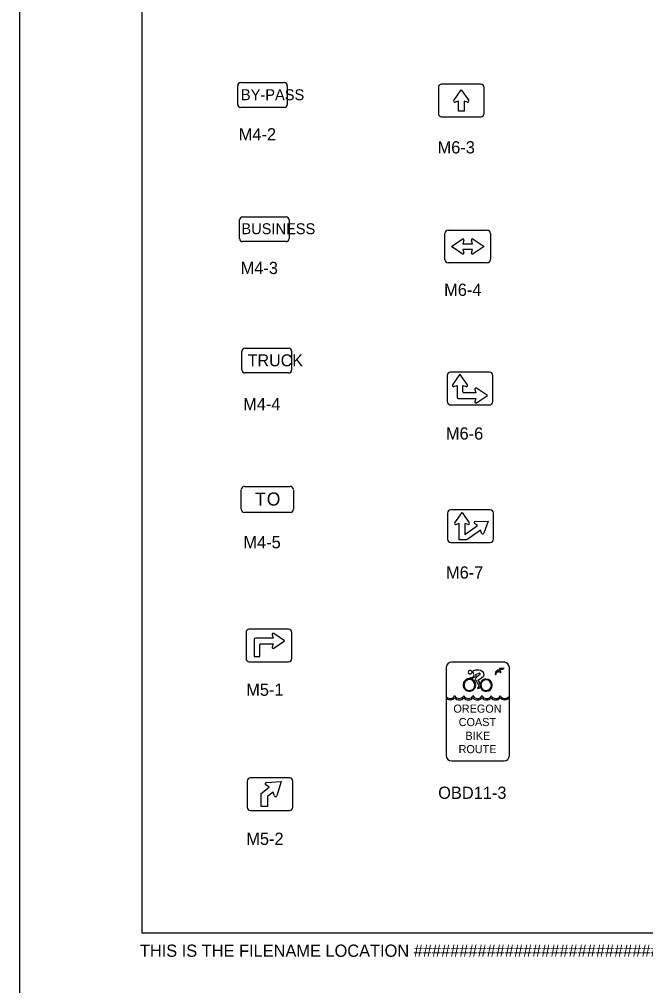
# Model space of a CAD drawing. Extents: x 42133 to 45533, y 41351 to 47951.
# Drawn here: x 42133 to 42517, y 44669 to 45261 of the extents above; entities that cross this region are included whole.
import ezdxf

# ---------------------------------------------------------------- set-up
doc = ezdxf.new("R2010")
doc.units = 0
for name, color, linetype in [('#plot_border', 7, 'Continuous'), ('#plot_shape', 7, 'Continuous'), ('P_ODOT_PLAN_Border', 7, 'Continuous'), ('P_TRAF_SIGN_SignDetails', 7, 'Continuous')]:
    doc.layers.add(name, color=color, linetype=linetype)

msp = doc.modelspace()

# ---------------------------------------------------------------- linework, layer by layer
at = {"layer": '#plot_shape'}
msp.add_lwpolyline([(42133.34, 44651.35), (43833.34, 44651.35), (43833.34, 45751.35), (42133.34, 45751.35)], close=True, dxfattribs=at)
at = {"layer": 'P_ODOT_PLAN_Border'}
msp.add_lwpolyline([(42208.34, 44701.35), (43808.34, 44701.35), (43808.34, 45701.35), (42208.34, 45701.35)], close=True, dxfattribs=at)
at = {"layer": 'P_TRAF_SIGN_SignDetails'}
for p, q in [((42267.07, 45209.07), (42267.07, 45220.48)), ((42268.98, 45222.38), (42295.58, 45222.38)), ((42297.48, 45220.48), (42297.48, 45209.07)), ((42390.03, 45219.48), (42390.03, 45203.48)), ((42416.01, 45221.48), (42392.02, 45221.48)), ((42418.01, 45203.48), (42418.01, 45219.48)), ((42399.47, 45211.36), (42404.01, 45217.99)), ((42404.01, 45217.99), (42408.56, 45211.36)), ((42295.58, 45207.17), (42268.98, 45207.17)), ((42402.27, 45210.97), (42400.21, 45210.35)), ((42402.27, 45204.98), (42402.27, 45210.97)), ((42407.82, 45210.35), (42405.76, 45210.97)), ((42405.76, 45210.97), (42405.76, 45204.98)), ((42392.02, 45201.49), (42416.01, 45201.49)), ((42405.76, 45204.98), (42402.27, 45204.98)), ((42268.18, 45126.87), (42268.18, 45138.27)), ((42270.09, 45140.17), (42296.7, 45140.17)), ((42298.6, 45138.27), (42298.6, 45126.87)), ((42394, 45113.94), (42394, 45129.94)), ((42395.99, 45131.94), (42419.98, 45131.94)), ((42421.98, 45129.94), (42421.98, 45113.94)), ((42296.7, 45124.96), (42270.09, 45124.96)), ((42398, 45121.94), (42404.62, 45126.48)), ((42405.63, 45125.74), (42405.01, 45123.68)), ((42410.97, 45123.68), (42410.35, 45125.74)), ((42411.37, 45126.48), (42417.99, 45121.94)), ((42404.62, 45117.39), (42398, 45121.94)), ((42405.01, 45123.68), (42410.97, 45123.68)), ((42410.97, 45120.19), (42405.01, 45120.19)), ((42405.01, 45120.19), (42405.63, 45118.14)), ((42410.35, 45118.14), (42410.97, 45120.19)), ((42417.99, 45121.94), (42411.37, 45117.39)), ((42419.98, 45111.94), (42395.99, 45111.94)), ((42271.59, 45059.67), (42298.2, 45059.67)), ((42269.69, 45046.37), (42269.69, 45057.77)), ((42300.1, 45057.77), (42300.1, 45046.37)), ((42298.2, 45044.46), (42271.59, 45044.46)), ((42395.36, 45042.85), (42395.36, 45026.86)), ((42421.34, 45044.85), (42397.36, 45044.85)), ((42403.23, 45043.78), (42398.69, 45037.16)), ((42407.78, 45037.16), (42403.23, 45043.78)), ((42423.34, 45026.86), (42423.34, 45042.85)), ((42399.43, 45036.14), (42401.48, 45036.76)), ((42401.48, 45036.76), (42401.48, 45029.59)), ((42404.99, 45032.84), (42404.98, 45036.76)), ((42404.98, 45036.76), (42407.04, 45036.14)), ((42420.05, 45030.59), (42413.44, 45035.14)), ((42413.03, 45032.33), (42405.49, 45032.33)), ((42412.41, 45034.4), (42413.03, 45032.33)), ((42413.44, 45026.04), (42420.05, 45030.59)), ((42397.36, 45024.86), (42421.34, 45024.86)), ((42402.23, 45028.84), (42413.03, 45028.84)), ((42413.03, 45028.84), (42412.41, 45026.78)), ((42413.43, 45026.04), (42413.44, 45026.04)), ((42269.22, 44960.91), (42269.22, 44972.92)), ((42271.22, 44974.92), (42299.23, 44974.92)), ((42301.24, 44972.92), (42301.24, 44960.91)), ((42299.23, 44958.92), (42271.22, 44958.92)), ((42395.69, 44958.55), (42395.69, 44942.56)), ((42421.67, 44960.55), (42397.69, 44960.55)), ((42400.08, 44952.54), (42404.52, 44959.01)), ((42400.08, 44952.54), (42404.52, 44959.01)), ((42400.08, 44952.54), (42404.52, 44959.01)), ((42404.52, 44959.01), (42408.96, 44952.54)), ((42404.52, 44959.01), (42408.96, 44952.54)), ((42404.52, 44959.01), (42408.96, 44952.54)), ((42423.67, 44942.56), (42423.67, 44958.55)), ((42397.69, 44940.56), (42421.67, 44940.56)), ((42298.19, 44887.47), (42274.21, 44887.47)), ((42272.21, 44885.48), (42272.21, 44869.49)), ((42277.19, 44881.23), (42277.19, 44870.6)), ((42288.74, 44881.97), (42277.93, 44881.97)), ((42288.12, 44884.03), (42288.74, 44881.97)), ((42295.75, 44880.23), (42289.14, 44884.77)), ((42300.19, 44869.49), (42300.19, 44885.48)), ((42280.69, 44870.6), (42280.69, 44877.97)), ((42281.2, 44878.48), (42288.74, 44878.48)), ((42288.74, 44878.48), (42288.12, 44876.42)), ((42289.14, 44875.68), (42295.75, 44880.23)), ((42277.19, 44870.6), (42280.69, 44870.6)), ((42274.21, 44867.49), (42298.19, 44867.49)), ((42394.82, 44863.94), (42394.82, 44809.76)), ((42430.64, 44867.15), (42398.03, 44867.15)), ((42433.51, 44809.8), (42433.51, 44864.13)), ((42410.67, 44860.91), (42410.63, 44860.74)), ((42405.2, 44853.73), (42405.73, 44853.63)), ((42405.73, 44853.63), (42405.2, 44853.73)), ((42412.41, 44853.03), (42412.88, 44853)), ((42415.58, 44853.62), (42416.02, 44853)), ((42416.16, 44852.22), (42415.74, 44851.84)), ((42419.26, 44856.32), (42419.26, 44856.83)), ((42419.26, 44856.32), (42419.26, 44856.83)), ((42395.04, 44844.79), (42395.02, 44845.86)), ((42419.38, 44849.39), (42419.37, 44849.86)), ((42433.02, 44845.92), (42433.05, 44844.85)), ((42397.95, 44806.68), (42430.27, 44806.68)), ((42272.91, 44794.24), (42272.91, 44778.25)), ((42298.89, 44796.24), (42274.91, 44796.24)), ((42300.89, 44778.25), (42300.89, 44794.24)), ((42274.91, 44776.25), (42298.89, 44776.25))]:
    msp.add_line(p, q, dxfattribs=at)
for points in [[(42416.51, 44946.22), (42415.86, 44948.2), (42407.41, 44942.14), (42402.83, 44942.14), (42402.83, 44952.15), (42400.84, 44951.52)], [(42416.51, 44946.22), (42415.86, 44948.2), (42407.41, 44942.14), (42402.83, 44942.14), (42402.83, 44952.15), (42400.84, 44951.52)], [(42416.51, 44946.22), (42415.86, 44948.2), (42407.41, 44942.14), (42402.83, 44942.14), (42402.83, 44952.15), (42400.84, 44951.52)], [(42408.19, 44951.52), (42406.21, 44952.15), (42406.21, 44945.43), (42413.89, 44950.94), (42412.22, 44952.19)], [(42408.19, 44951.52), (42406.21, 44952.15), (42406.21, 44945.43), (42413.89, 44950.94), (42412.22, 44952.19)], [(42408.19, 44951.52), (42406.21, 44952.15), (42406.21, 44945.43), (42413.89, 44950.94), (42412.22, 44952.19)], [(42412.61, 44953.41), (42420.45, 44953.57), (42417.79, 44946.2)], [(42412.61, 44953.41), (42420.45, 44953.57), (42417.79, 44946.2)], [(42412.61, 44953.41), (42420.45, 44953.57), (42417.79, 44946.2)], [(42284.66, 44793.46), (42293.79, 44794.1), (42291.09, 44785.35)], [(42284.66, 44793.46), (42293.79, 44794.1), (42291.09, 44785.35)], [(42284.66, 44793.46), (42293.79, 44794.1), (42291.09, 44785.35)], [(42289.61, 44785.31), (42288.74, 44787.58), (42285.36, 44784.9), (42285.36, 44778.82), (42281.42, 44778.82), (42281.42, 44786.8), (42286.3, 44790.66), (42284.28, 44792.03)], [(42289.61, 44785.31), (42288.74, 44787.58), (42285.36, 44784.9), (42285.36, 44778.82), (42281.42, 44778.82), (42281.42, 44786.8), (42286.3, 44790.66), (42284.28, 44792.03)], [(42289.61, 44785.31), (42288.74, 44787.58), (42285.36, 44784.9), (42285.36, 44778.82), (42281.42, 44778.82), (42281.42, 44786.8), (42286.3, 44790.66), (42284.28, 44792.03)]]:
    msp.add_lwpolyline(points, dxfattribs=at)
for centre, radius, start, end in [((42268.97, 45220.48), 1.9, 90, 180), ((42295.58, 45220.48), 1.9, 0, 90), ((42392.02, 45219.48), 2, 90, 180), ((42416.01, 45219.48), 2, 360, 90), ((42268.97, 45209.07), 1.9, 180, 270), ((42295.58, 45209.07), 1.9, 270, 0), ((42400.02, 45210.99), 0.666, 145.51241, 286.7372), ((42408.01, 45210.99), 0.666, 253.2628, 34.48759), ((42392.02, 45203.49), 2, 180, 270), ((42416.01, 45203.49), 2, 270, 0), ((42270.08, 45138.27), 1.9, 90, 180), ((42296.69, 45138.27), 1.9, 0, 90), ((42395.99, 45129.93), 2, 90, 180), ((42419.98, 45129.93), 2, 0, 90), ((42270.08, 45126.87), 1.9, 180, 270), ((42296.69, 45126.87), 1.9, 270, 0), ((42404.99, 45125.94), 0.666, 343.2628, 124.48759), ((42410.99, 45125.94), 0.666, 55.51241, 196.7372), ((42404.99, 45117.94), 0.666, 235.51241, 16.7372), ((42410.99, 45117.94), 0.666, 163.2628, 304.48759), ((42395.99, 45113.94), 2, 180, 270), ((42419.98, 45113.94), 2, 270, 360), ((42271.59, 45057.77), 1.9, 90, 180), ((42298.2, 45057.77), 1.9, 0, 90), ((42271.59, 45046.37), 1.9, 180, 270), ((42298.2, 45046.37), 1.9, 270, 0), ((42397.36, 45042.85), 2, 90, 180), ((42421.34, 45042.85), 2, 360, 90), ((42399.23, 45036.78), 0.666, 145.51241, 286.7372), ((42407.23, 45036.78), 0.666, 253.2628, 34.48759), ((42413.05, 45034.59), 0.666, 55.51241, 196.7372), ((42402.23, 45029.59), 0.746, 180, 270), ((42405.49, 45032.84), 0.506, 180, 270), ((42397.36, 45026.86), 2, 180, 270), ((42413.05, 45026.59), 0.666, 163.2628, 304.48759), ((42421.34, 45026.86), 2, 270, 0), ((42271.22, 44972.93), 2, 90, 180), ((42299.23, 44972.93), 2, 360, 90), ((42271.22, 44960.92), 2, 180, 270), ((42299.23, 44960.92), 2, 270, 360), ((42397.69, 44958.55), 2, 90, 180), ((42421.67, 44958.55), 2, 360, 90), ((42397.69, 44942.56), 2, 180, 270), ((42421.67, 44942.56), 2, 270, 0), ((42274.21, 44885.47), 2, 90, 180), ((42298.2, 44885.47), 2, 360, 90), ((42277.93, 44881.22), 0.746, 90, 180), ((42288.76, 44884.22), 0.666, 55.51241, 196.7372), ((42281.2, 44877.97), 0.506, 90, 180), ((42288.76, 44876.23), 0.666, 163.2628, 304.48759), ((42274.21, 44869.48), 2, 180, 270), ((42298.2, 44869.48), 2, 270, 0), ((42398.1, 44863.87), 3.28, 90, 176.98392), ((42398.1, 44863.87), 3.28, 176.98392, 180), ((42427.72, 44863.11), 0.267, 55.09984, 178.03026), ((42426.99, 44794.51), 68.82, 87.32377, 89.26629), ((42429.61, 44863.7), 0.736, 277.87393, 323.3106), ((42430.23, 44863.87), 3.28, 360, 90), ((42409.67, 44857.15), 0.509, 146.6757, 183.53735), ((42411.09, 44852.31), 5.44, 99.74793, 109.64671), ((42410.03, 44859.52), 1.84, 274.30157, 344.79689), ((42411.76, 44856.61), 1.15, 134.17087, 167.71993), ((42418.69, 44840.45), 18.66, 108.0677, 114.45218), ((42412.29, 44861.2), 1.13, 143.40254, 210.69902), ((42410.03, 44859.36), 1.81, 349.95685, 44.56741), ((42414.17, 44854.23), 8.14, 95.65153, 110.03117), ((42420.13, 44851.62), 9.23, 121.24992, 144.13962), ((42411.14, 44859), 1.94, 336.10404, 22.65986), ((42411.1, 44868.83), 9.26, 281.40372, 292.53029), ((42413.81, 44856.57), 5.77, 47.07871, 94.07318), ((42406.92, 44870.59), 16.14, 296.80103, 310.70014), ((42414.97, 44859.77), 0.623, 24.66568, 120.91866), ((42415.23, 44859.86), 0.368, 288.16063, 27.61072), ((42415.71, 44859.79), 2.26, 320.47777, 26.47607), ((42426.16, 44860.16), 1.32, 161.07967, 208.26866), ((42426.39, 44860.68), 1.47, 144.28592, 183.50768), ((42424.73, 44860.14), 0.657, 294.08836, 340.32682), ((42423.61, 44871.79), 10.37, 278.77404, 284.00291), ((42424.92, 44860.08), 0.458, 338.64936, 38.4327), ((42424.61, 44861.01), 0.94, 316.99959, 356.87468), ((42425.24, 44863.3), 2.36, 277.50421, 305.41891), ((42425.65, 44862.87), 0.77, 289.94858, 318.13199), ((42426.11, 44862.44), 0.349, 235.87836, 288.89222), ((42426.11, 44862.12), 0.395, 271.27035, 332.03771), ((42425.68, 44860.06), 2.36, 63.03764, 76.67919), ((42426.14, 44861.74), 0.374, 30.96984, 75.95273), ((42426.81, 44860.34), 1.05, 43.84297, 101.18103), ((42425.88, 44863.8), 1.87, 298.15666, 316.41489), ((42424.89, 44863.75), 2.64, 331.97589, 346.19902), ((42427.96, 44861.41), 0.512, 220.96473, 283.62721), ((42416.1, 44869.73), 13.99, 325.41501, 331.47073), ((42427.92, 44861.79), 0.3, 179.05314, 213.42455), ((42428, 44861.7), 0.335, 193.69222, 253.0807), ((42427.95, 44860.94), 0.446, 18.31889, 96.99566), ((42428.15, 44861.12), 0.227, 251.60885, 345.61206), ((42429.25, 44869.64), 6.65, 262.65616, 269.96826), ((42429.45, 44862.46), 0.576, 62.8144, 112.05217), ((42409.03, 44853.25), 3.86, 172.7669, 356.38345), ((42409.03, 44853.25), 3.86, 356.38345, 172.7669), ((42409.06, 44853.23), 3.35, 173.21648, 356.60824), ((42409.06, 44853.23), 3.35, 356.60824, 173.21648), ((42409.52, 44854.91), 2.24, 60.06858, 99.06921), ((42413.48, 44856.75), 0.855, 161.36642, 215.68311), ((43449.83, 45477.33), 1208.81, 210.91709, 211.10201), ((42418.58, 44847.8), 5.82, 129.99018, 142.87914), ((42413.05, 44850.63), 1.12, 22.77022, 37.05707), ((42413.25, 44855), 4.02, 281.87372, 308.4864), ((42411.13, 44852.88), 4.52, 9.34413, 46.9844), ((42414.3, 44852.55), 0.61, 332.46428, 36.08466), ((42419.26, 44853.11), 3.72, 90, 271.98753), ((42411.39, 44850.2), 5.41, 24.11035, 31.16963), ((42419.26, 44853.09), 3.23, 90, 272.01063), ((42413.25, 44855), 4.02, 316.28841, 319.86775), ((42419.26, 44853.11), 3.72, 271.98753, 90), ((42419.26, 44853.09), 3.23, 272.01063, 90), ((42397.23, 44848), 3.08, 224.10748, 335.06367), ((42402.82, 44848), 3.08, 204.86849, 335.06367), ((42408.4, 44848), 3.08, 204.86849, 335.06367), ((42413.98, 44847.99), 3.08, 204.86849, 335.06367), ((42419.57, 44847.99), 3.08, 204.86849, 335.06367), ((42425.15, 44847.99), 3.08, 204.86849, 335.06367), ((42430.73, 44847.98), 3.08, 204.86849, 318.0148), ((42397.23, 44848), 3.89, 235.69056, 315.81148), ((42402.82, 44848), 3.89, 224.12067, 315.81148), ((42408.4, 44848), 3.89, 224.12067, 315.81148), ((42413.98, 44847.99), 3.89, 224.12067, 315.81148), ((42419.57, 44847.99), 3.89, 224.12067, 315.81148), ((42425.15, 44847.99), 3.89, 224.12067, 315.81148), ((42430.73, 44847.98), 3.89, 224.12067, 306.45538), ((42398.1, 44809.96), 3.28, 180, 270), ((42430.23, 44809.96), 3.28, 270, 0), ((42274.91, 44794.24), 2, 90, 180), ((42298.89, 44794.24), 2, 360, 90), ((42274.91, 44778.25), 2, 180, 270), ((42298.89, 44778.25), 2, 270, 0)]:
    msp.add_arc(centre, radius, start, end, dxfattribs=at)
for centre, major_axis, ratio, start_param, end_param in [((42400.64, 44952.16), (0.675, 0), 0.999925, 2.54034, 5.019584), ((42400.64, 44952.16), (0.675, 0), 0.999925, 2.54034, 5.019584), ((42400.64, 44952.16), (0.675, 0), 0.999925, 2.54034, 5.019584), ((42408.4, 44952.16), (0.675, 0), 0.999925, 4.405194, 6.884438), ((42408.4, 44952.16), (0.675, 0), 0.999925, 4.405194, 6.884438), ((42408.4, 44952.16), (0.675, 0), 0.999925, 4.405194, 6.884438), ((42412.63, 44952.73), (0.675, 0), 0.999925, 1.592016, 4.071259), ((42412.63, 44952.73), (0.675, 0), 0.999925, 1.592016, 4.071259), ((42412.63, 44952.73), (0.675, 0), 0.999925, 1.592016, 4.071259), ((42417.15, 44946.43), (0.675, 0), 0.999925, 3.45687, 5.936113), ((42417.15, 44946.43), (0.675, 0), 0.999925, 3.45687, 5.936113), ((42417.15, 44946.43), (0.675, 0), 0.999925, 3.45687, 5.936113), ((42409.47, 44861.07), (1.2, -0.17), 0.841982, 2.801513, 6.283185), ((42409.47, 44861.07), (1.2, -0.17), 0.841982, 6.11218, 9.084698), ((42284.72, 44792.68), (0.787, 0), 0.999925, 1.639875, 4.119118), ((42284.72, 44792.68), (0.787, 0), 0.999925, 1.639875, 4.119118), ((42284.72, 44792.68), (0.787, 0), 0.999925, 1.639875, 4.119118), ((42290.34, 44785.58), (0.787, 0), 0.999925, 3.504729, 5.983972), ((42290.34, 44785.58), (0.787, 0), 0.999925, 3.504729, 5.983972), ((42290.34, 44785.58), (0.787, 0), 0.999925, 3.504729, 5.983972)]:
    msp.add_ellipse(centre, major_axis=major_axis, ratio=ratio, start_param=start_param, end_param=end_param, dxfattribs=at)

# ---------------------------------------------------------------- texts
at = {"layer": '#plot_border'}
msp.add_text('THIS IS THE FILENAME LOCATION ##############################     DD-MMM-YYYY  HH:MM     USERNAME', height=7.5, dxfattribs=at).set_placement((42207.17, 44686.62))
at = {"layer": 'P_TRAF_SIGN_SignDetails'}
for s, height, p in [('BY-PASS', 6.697, (42269.05, 45211.62)), ('M4-2', 7.5, (42267.73, 45186.97)), ('M6-3', 7.5, (42389.51, 45178.99)), ('BUSINESS', 6.697, (42269.34, 45129.5)), ('M4-3', 7.5, (42268.89, 45105.07)), ('M6-4', 7.5, (42393.54, 45091.69)), ('TRUCK', 7.367, (42273.2, 45048.51)), ('M4-4', 7.5, (42270.44, 45021.63)), ('M6-6', 7.5, (42394.62, 45003.61)), ('T', 8, (42277.72, 44963.12)), ('O', 8, (42284.9, 44963.2)), ('M4-5', 7.5, (42270.6, 44936.97)), ('M6-7', 7.5, (42394.68, 44918.43)), ('M5-1', 7.5, (42272.3, 44846.58)), ('OREGON', 4.959, (42399.22, 44836.24)), ('COAST', 4.959, (42402.47, 44828.01)), ('BIKE', 4.959, (42406.63, 44819.6)), ('ROUTE', 4.959, (42402.4, 44811.44)), ('OBD11-3', 7.5, (42389.89, 44783.42)), ('M5-2', 7.5, (42272.35, 44755.22))]:
    msp.add_text(s, height=height, dxfattribs=at).set_placement(p)

doc.saveas('drawing.dxf')
